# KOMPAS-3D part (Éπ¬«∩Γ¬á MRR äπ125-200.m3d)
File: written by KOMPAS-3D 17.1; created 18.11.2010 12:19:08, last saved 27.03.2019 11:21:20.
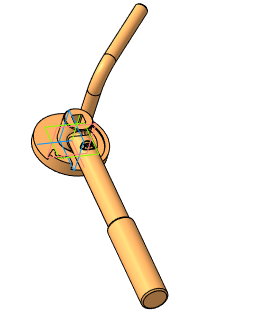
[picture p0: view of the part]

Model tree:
1. Плоскость XY
2. Плоскость ZX
3. Плоскость ZY
4. Ось X
5. Ось Y
6. Ось Z
7. Начало координат
8. Операция без истории:2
